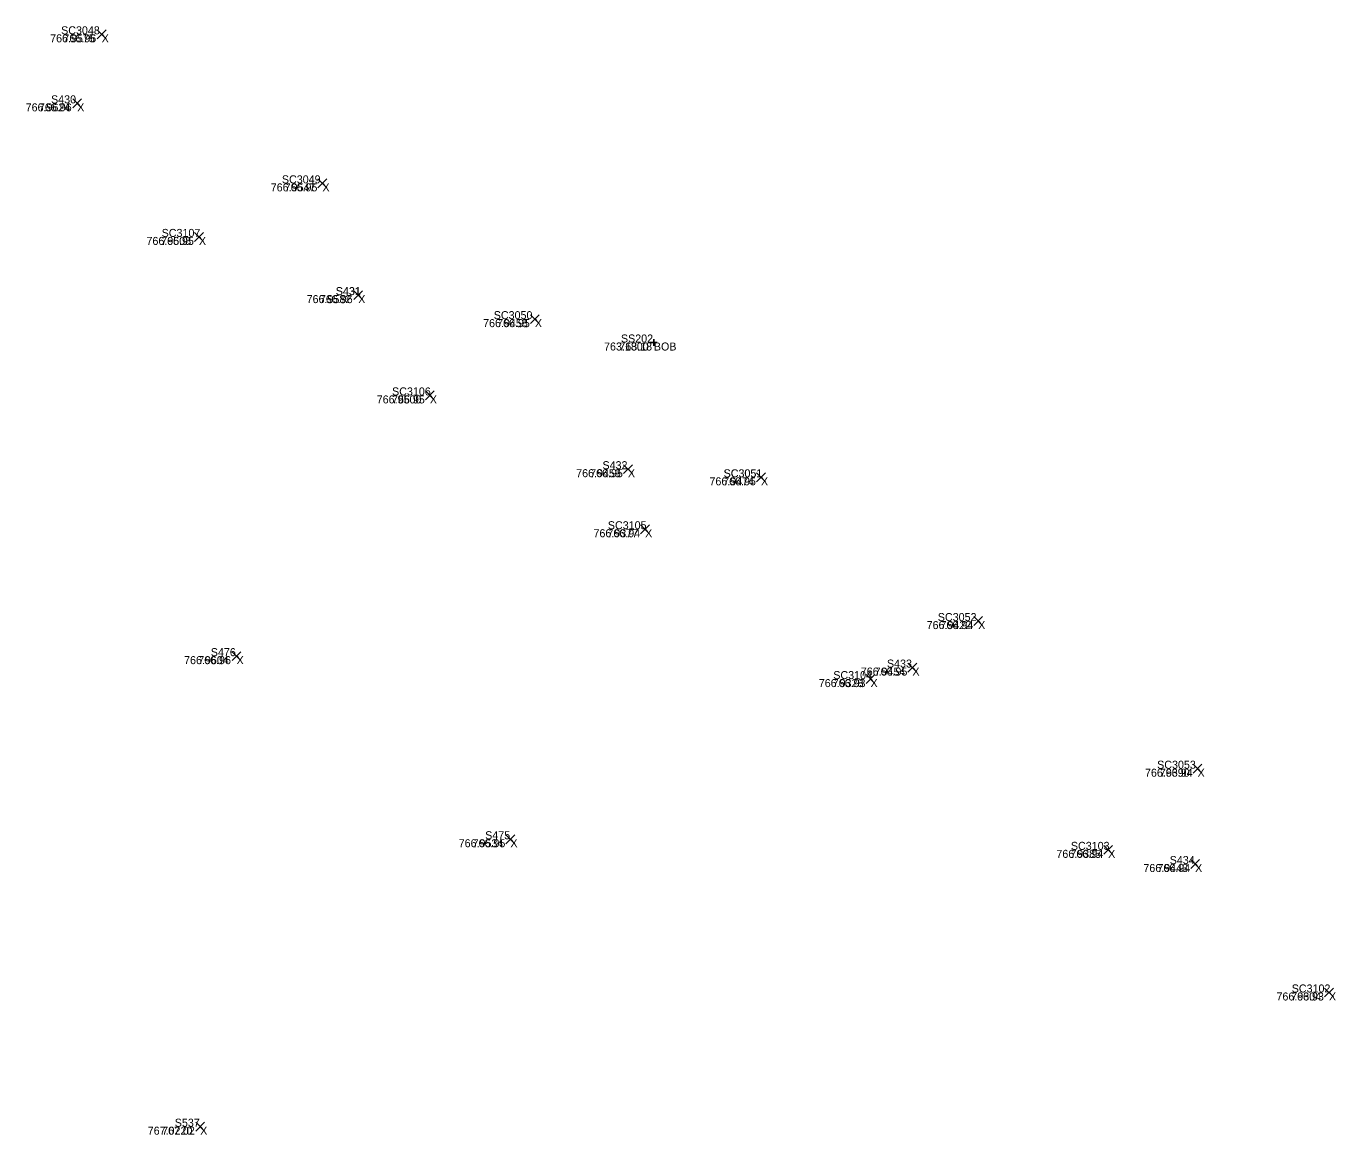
# Model space of a CAD drawing. Extents: x 1845019 to 1877956, y 680444 to 701081.
# Drawn here: x 1857780.56 to 1857790.38, y 694212.5 to 694220.81 of the extents above; entities that cross this region are included whole.
import ezdxf

# ---------------------------------------------------------------- set-up
doc = ezdxf.new("R2010")
doc.units = 0
for name, color, linetype in [('BR_X_SV_Bottom_of_Beam_Text', 7, 'Continuous'), ('SV_X_Random_Point', 7, 'Continuous'), ('SV_X_Text_Comment', 7, 'Continuous'), ('SV_X_Text_Elevation', 7, 'Continuous'), ('SV_X_Text_Name', 7, 'Continuous')]:
    doc.layers.add(name, color=color, linetype=linetype)

msp = doc.modelspace()

# ---------------------------------------------------------------- linework, layer by layer
at = {"layer": 'BR_X_SV_Bottom_of_Beam_Text'}
for p, q in [((1857785.2397, 694218.4409), (1857785.2897, 694218.4409)), ((1857785.2397, 694218.4409), (1857785.2897, 694218.4409)), ((1857785.2647, 694218.4659), (1857785.2647, 694218.4159)), ((1857785.2647, 694218.4659), (1857785.2647, 694218.4159)), ((1857785.2647, 694218.4409), (1857785.2647, 694218.4409)), ((1857785.2647, 694218.4409), (1857785.2647, 694218.4409))]:
    msp.add_line(p, q, dxfattribs=at)
at = {"layer": 'SV_X_Random_Point'}
for p, q in [((1857781.0924, 694220.7176), (1857781.159, 694220.7844)), ((1857781.0924, 694220.7844), (1857781.159, 694220.7176)), ((1857781.0924, 694220.7176), (1857781.159, 694220.7844)), ((1857781.0924, 694220.7844), (1857781.159, 694220.7176)), ((1857780.9091, 694220.2002), (1857780.9757, 694220.267)), ((1857780.9091, 694220.267), (1857780.9757, 694220.2002)), ((1857780.9091, 694220.2002), (1857780.9757, 694220.267)), ((1857780.9091, 694220.267), (1857780.9757, 694220.2002)), ((1857782.7472, 694219.6003), (1857782.8138, 694219.6671)), ((1857782.7472, 694219.6671), (1857782.8138, 694219.6003)), ((1857782.7472, 694219.6003), (1857782.8138, 694219.6671)), ((1857782.7472, 694219.6671), (1857782.8138, 694219.6003)), ((1857781.8214, 694219.1989), (1857781.888, 694219.2657)), ((1857781.8214, 694219.2657), (1857781.888, 694219.1989)), ((1857781.8214, 694219.1989), (1857781.888, 694219.2657)), ((1857781.8214, 694219.2657), (1857781.888, 694219.1989)), ((1857783.0153, 694218.7626), (1857783.0819, 694218.8294)), ((1857783.0153, 694218.8294), (1857783.0819, 694218.7626)), ((1857783.0153, 694218.7626), (1857783.0819, 694218.8294)), ((1857783.0153, 694218.8294), (1857783.0819, 694218.7626)), ((1857784.3394, 694218.5825), (1857784.406, 694218.6493)), ((1857784.3394, 694218.6493), (1857784.406, 694218.5825)), ((1857784.3394, 694218.5825), (1857784.406, 694218.6493)), ((1857784.3394, 694218.6493), (1857784.406, 694218.5825)), ((1857783.5521, 694218.0108), (1857783.6187, 694218.0776)), ((1857783.5521, 694218.0776), (1857783.6187, 694218.0108)), ((1857783.5521, 694218.0108), (1857783.6187, 694218.0776)), ((1857783.5521, 694218.0776), (1857783.6187, 694218.0108)), ((1857785.0369, 694217.4578), (1857785.1035, 694217.5246)), ((1857785.0369, 694217.5246), (1857785.1035, 694217.4578)), ((1857785.0369, 694217.4578), (1857785.1035, 694217.5246)), ((1857785.0369, 694217.5246), (1857785.1035, 694217.4578)), ((1857786.0342, 694217.3969), (1857786.1008, 694217.4637)), ((1857786.0342, 694217.4637), (1857786.1008, 694217.3969)), ((1857786.0342, 694217.3969), (1857786.1008, 694217.4637)), ((1857786.0342, 694217.4637), (1857786.1008, 694217.3969)), ((1857785.1658, 694217.0077), (1857785.2324, 694217.0745)), ((1857785.1658, 694217.0745), (1857785.2324, 694217.0077)), ((1857785.1658, 694217.0077), (1857785.2324, 694217.0745)), ((1857785.1658, 694217.0745), (1857785.2324, 694217.0077)), ((1857787.6622, 694216.3194), (1857787.7288, 694216.3862)), ((1857787.6622, 694216.3862), (1857787.7288, 694216.3194)), ((1857787.6622, 694216.3194), (1857787.7288, 694216.3862)), ((1857787.6622, 694216.3862), (1857787.7288, 694216.3194)), ((1857782.1032, 694216.0564), (1857782.1698, 694216.1232)), ((1857782.1032, 694216.1232), (1857782.1698, 694216.0564)), ((1857782.1032, 694216.0564), (1857782.1698, 694216.1232)), ((1857782.1032, 694216.1232), (1857782.1698, 694216.0564)), ((1857787.1693, 694215.9709), (1857787.2359, 694216.0377)), ((1857787.1693, 694216.0377), (1857787.2359, 694215.9709)), ((1857787.1693, 694215.9709), (1857787.2359, 694216.0377)), ((1857787.1693, 694216.0377), (1857787.2359, 694215.9709)), ((1857786.8551, 694215.8845), (1857786.9217, 694215.9513)), ((1857786.8551, 694215.9513), (1857786.9217, 694215.8845)), ((1857786.8551, 694215.8845), (1857786.9217, 694215.9513)), ((1857786.8551, 694215.9513), (1857786.9217, 694215.8845)), ((1857789.3067, 694215.2127), (1857789.3733, 694215.2795)), ((1857789.3067, 694215.2795), (1857789.3733, 694215.2127)), ((1857789.3067, 694215.2127), (1857789.3733, 694215.2795)), ((1857789.3067, 694215.2795), (1857789.3733, 694215.2127)), ((1857784.156, 694214.6841), (1857784.2226, 694214.7509)), ((1857784.156, 694214.7509), (1857784.2226, 694214.6841)), ((1857784.156, 694214.6841), (1857784.2226, 694214.7509)), ((1857784.156, 694214.7509), (1857784.2226, 694214.6841)), ((1857788.6365, 694214.6045), (1857788.7031, 694214.6713)), ((1857788.6365, 694214.6713), (1857788.7031, 694214.6045)), ((1857788.6365, 694214.6045), (1857788.7031, 694214.6713)), ((1857788.6365, 694214.6713), (1857788.7031, 694214.6045)), ((1857789.2885, 694214.4984), (1857789.3551, 694214.5652)), ((1857789.2885, 694214.5652), (1857789.3551, 694214.4984)), ((1857789.2885, 694214.4984), (1857789.3551, 694214.5652)), ((1857789.2885, 694214.5652), (1857789.3551, 694214.4984)), ((1857790.2912, 694213.5355), (1857790.3578, 694213.6023)), ((1857790.2912, 694213.6023), (1857790.3578, 694213.5355)), ((1857790.2912, 694213.5355), (1857790.3578, 694213.6023)), ((1857790.2912, 694213.6023), (1857790.3578, 694213.5355)), ((1857781.8308, 694212.5294), (1857781.8974, 694212.5962)), ((1857781.8308, 694212.5962), (1857781.8974, 694212.5294)), ((1857781.8308, 694212.5294), (1857781.8974, 694212.5962)), ((1857781.8308, 694212.5962), (1857781.8974, 694212.5294))]:
    msp.add_line(p, q, dxfattribs=at)

# ---------------------------------------------------------------- texts
at = {"layer": 'BR_X_SV_Bottom_of_Beam_Text'}
for s, p in [('SS202', (1857785.0181, 694218.4409)), ('SS202', (1857785.0181, 694218.4409)), ('763.1800', (1857784.8915, 694218.3809)), ('763.18', (1857785.0058, 694218.3809)), ('BOB', (1857785.2647, 694218.3809))]:
    msp.add_text(s, height=0.06, dxfattribs=at).set_placement(p)
at = {"layer": 'SV_X_Text_Comment'}
for p in [(1857781.1257, 694220.691), (1857780.9424, 694220.1736), (1857782.7805, 694219.5737), (1857781.8547, 694219.1723), (1857783.0486, 694218.736), (1857784.3727, 694218.5559), (1857783.5854, 694217.9842), (1857785.0702, 694217.4312), (1857786.0675, 694217.3703), (1857785.1991, 694216.9811), (1857787.6955, 694216.2928), (1857782.1365, 694216.0298), (1857787.2026, 694215.9443), (1857786.8884, 694215.8579), (1857789.34, 694215.1861), (1857784.1893, 694214.6575), (1857788.6698, 694214.5779), (1857789.3218, 694214.4718), (1857790.3245, 694213.5089), (1857781.8641, 694212.5028)]:
    msp.add_text('X', height=0.06, dxfattribs=at).set_placement(p)
at = {"layer": 'SV_X_Text_Elevation'}
for s, p in [('766.9575', (1857780.7397, 694220.691)), ('766.96', (1857780.8389, 694220.691)), ('766.9624', (1857780.556, 694220.1736)), ('766.96', (1857780.6556, 694220.1736)), ('766.9547', (1857782.3931, 694219.5737)), ('766.95', (1857782.4975, 694219.5737)), ('766.9508', (1857781.4617, 694219.1723)), ('766.95', (1857781.5717, 694219.1723)), ('766.9582', (1857782.6622, 694218.736)), ('766.96', (1857782.7618, 694218.736)), ('766.9458', (1857783.9849, 694218.5559)), ('766.95', (1857784.0897, 694218.5559)), ('766.9500', (1857783.1876, 694217.9842)), ('766.95', (1857783.3024, 694217.9842)), ('766.9459', (1857784.6824, 694217.4312)), ('766.95', (1857784.7872, 694217.4312)), ('766.9474', (1857785.6815, 694217.3703)), ('766.95', (1857785.7845, 694217.3703)), ('766.9377', (1857784.8122, 694216.9811)), ('766.94', (1857784.9166, 694216.9811)), ('766.9422', (1857787.3095, 694216.2928)), ('766.94', (1857787.413, 694216.2928)), ('766.9604', (1857781.7435, 694216.0298)), ('766.96', (1857781.8497, 694216.0298)), ('766.9454', (1857786.8157, 694215.9443)), ('766.95', (1857786.9196, 694215.9443)), ('766.9328', (1857786.501, 694215.8579)), ('766.93', (1857786.6054, 694215.8579)), ('766.9390', (1857788.946, 694215.1861)), ('766.94', (1857789.0575, 694215.1861)), ('766.9534', (1857783.8019, 694214.6575)), ('766.95', (1857783.9063, 694214.6575)), ('766.9385', (1857788.282, 694214.5779)), ('766.94', (1857788.3873, 694214.5779)), ('766.9443', (1857788.934, 694214.4718)), ('766.94', (1857789.0393, 694214.4718)), ('766.9304', (1857789.9315, 694213.5089)), ('766.93', (1857790.0415, 694213.5089)), ('767.0220', (1857781.4711, 694212.5028)), ('767.02', (1857781.5788, 694212.5028))]:
    msp.add_text(s, height=0.06, dxfattribs=at).set_placement(p)
at = {"layer": 'SV_X_Text_Name'}
for s, p in [('SC3048', (1857780.8219, 694220.751)), ('SC3048', (1857780.8219, 694220.751)), ('S430', (1857780.7464, 694220.2336)), ('S430', (1857780.7464, 694220.2336)), ('SC3049', (1857782.4767, 694219.6337)), ('SC3049', (1857782.4767, 694219.6337)), ('SC3107', (1857781.5755, 694219.2323)), ('SC3107', (1857781.5755, 694219.2323)), ('S431', (1857782.8803, 694218.796)), ('S431', (1857782.8812, 694218.796)), ('SC3050', (1857784.0647, 694218.6159)), ('SC3050', (1857784.0647, 694218.6159)), ('SC3106', (1857783.3025, 694218.0442)), ('SC3106', (1857783.3025, 694218.0442)), ('S432', (1857784.8798, 694217.4912)), ('S432', (1857784.8798, 694217.4912)), ('SC3051', (1857785.7872, 694217.4303)), ('SC3051', (1857785.7882, 694217.4303)), ('SC3105', (1857784.9199, 694217.0411)), ('SC3105', (1857784.9199, 694217.0411)), ('SC3052', (1857787.3932, 694216.3528)), ('SC3052', (1857787.3932, 694216.3528)), ('S476', (1857781.9438, 694216.0898)), ('S476', (1857781.9438, 694216.0898)), ('S433', (1857787.0118, 694216.0043)), ('S433', (1857787.0118, 694216.0043)), ('SC3104', (1857786.6097, 694215.9179)), ('SC3104', (1857786.6097, 694215.9179)), ('SC3053', (1857789.0372, 694215.2461)), ('SC3053', (1857789.0372, 694215.2461)), ('S475', (1857784.0003, 694214.7175)), ('S475', (1857784.0003, 694214.7175)), ('SC3103', (1857788.3906, 694214.6379)), ('SC3103', (1857788.3906, 694214.6379)), ('S434', (1857789.1314, 694214.5318)), ('S434', (1857789.1314, 694214.5318)), ('SC3102', (1857790.0458, 694213.5689)), ('SC3102', (1857790.0458, 694213.5689)), ('S537', (1857781.6737, 694212.5628)), ('S537', (1857781.6737, 694212.5628))]:
    msp.add_text(s, height=0.06, dxfattribs=at).set_placement(p)

doc.saveas('drawing.dxf')
